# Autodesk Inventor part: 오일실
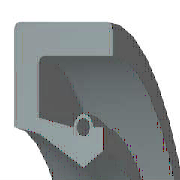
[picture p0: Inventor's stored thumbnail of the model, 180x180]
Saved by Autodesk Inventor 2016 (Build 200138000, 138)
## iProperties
IsCustomPart: 0
Created: 2009-02
Part Number: 오일실
Material: 고무
Description: 오일-실
Document SubType Name: Modeling
Standard: KS B 2804
Standards Organization: KS
Language: ko-KR
Size Designation: S - 17 30 8
Categories: <MemberInstance><Categories><Category DisplayName="샤프트 부품" InternalName="7f7aeb1f-a693-4053-b835-cee3144e0d98" Mnemonic="SHFT"><Category DisplayName="실링" Intern
Density: 0.93 g/cm^3
Appearance: 고무 - 검은색 - 버전 1.1
Author: pww
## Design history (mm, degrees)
revolve "본체" stored, may be unused: angle "d17" = 90 deg
revolve "스프링1" stored, may be unused: angle "d18" = 90 deg
body "Solid1"
sketch "스케치1"
  geometry: L1 (0, 15)-(8, 15); L2 (8, 15)-(8, 13.75); L3 (8, 13.75)-(1.75, 13.75); L4 (0, 15)-(0, 10.6); L5 (0, 10.6)-(1.75, 10.25); L6 (1.75, 10.25)-(4.9, 8.5); L7 (4.9, 8.5)-(0, 8.5); L8 (6.3, 9.375)-(6.3, 10.6); L9 (0, 0)-(9.586, 0) reference; L10 (4.9, 8.5)-(6.3, 9.375); L11 (0, 18)-(0, -3) reference; L12 (-1.917, 0)-(11.503, 0) reference; L13 (4.2, 10.6)-(1.75, 11.09); L14 (1.75, 11.09)-(1.75, 13.75); L15 (6.3, 10.6)-(5.6, 10.6); C1 r 0.455 at (4.9, 10.6); A1 r 0.7 centre (4.9, 10.6) between (5.6, 10.6) and (4.2, 10.6)
  constraints: 26 end point, 5 horizontal alignment, 4 perpendicular, 2 centre point, 2 collinear, 2 horizontal, 2 parallel, 2 point on circle, 2 point on line, 2 vertical alignment, 1 coincident
  dimensions: "d0" = 30 diameter of L1 L9 (= SD2); "d1" = 18.75 diameter of L8.start L9 (= ABDM); "d2" = 1.25 distance of L1.end L2.end (computed from SD); "d3" = 0.91 diameter of C1 (= SPDI); "d4" = 1.4 diameter of A1 (= SPDA); "d5" = 17 diameter of L6.end L9 (= NND); "d6" = 20.5 diameter of L5.end L9 (= TKDM); "d7" = 21.2 diameter of L4.end L9 (= HLDM); "d8" = 4.9 distance from line of C1.centre L4 (= SPDST); "d9" = 6.3 distance between parallel lines of L8 L4 (= SDI); "d10" = 8 distance between parallel lines of L2 L4 (= SWDT); "d12" = 1.75 distance between parallel lines of L14 L4 (= SD)
fillet "모깎기1" dims "d11" = 0.3 (= RR)
other parameters: "SD2" = 30 [user parameter; used in 1 equation term], "SWDT" = 8 [user parameter; used in 1 equation term], "RR" = 0.3 [user parameter; used in 1 equation term], "SD" = 1.75 [user parameter; used in 2 equation terms], "NND" = 17 [user parameter; used in 1 equation term], "SPDA" = 1.4 [user parameter; used in 1 equation term], "SPDI" = 0.91 [user parameter; used in 1 equation term], "TKDM" = 20.5 [user parameter; used in 1 equation term], "HLDM" = 21.2 [user parameter; used in 1 equation term], "ABDM" = 18.75 [user parameter; used in 1 equation term], "SDI" = 6.3 [user parameter; used in 1 equation term], "SPDST" = 4.9 [user parameter; used in 1 equation term], "d13" = 0, "d14" = 0, "d15" = 0, "LAB" = 0.35 [user parameter]
